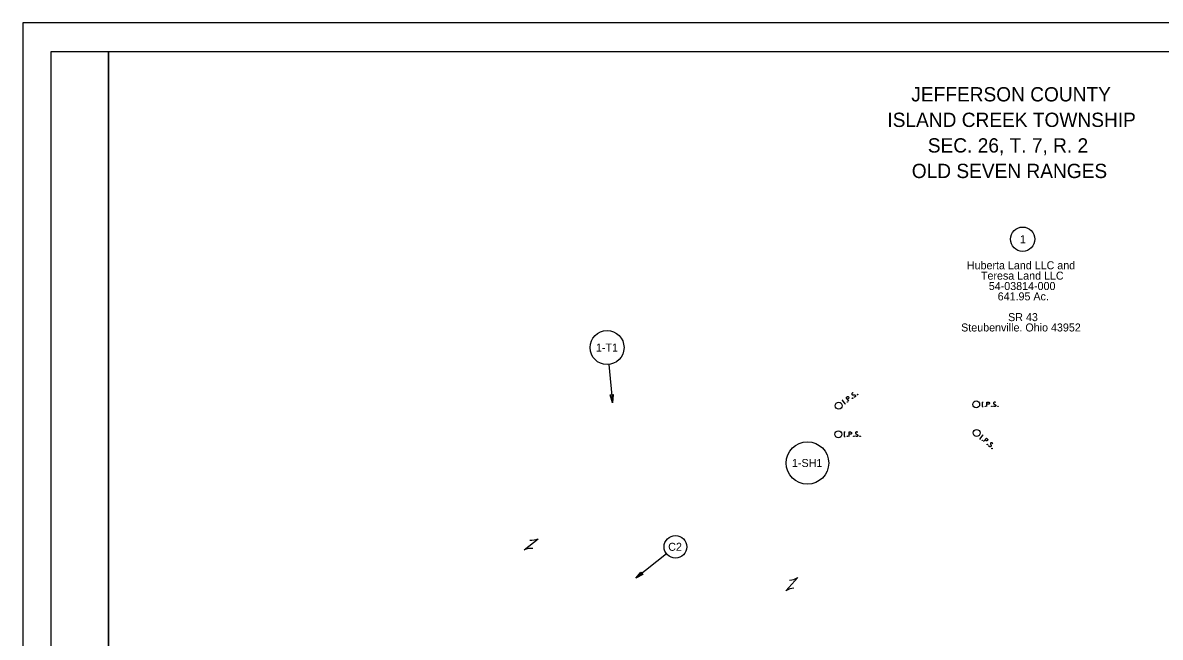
# Model space of a CAD drawing. Extents: x 0 to 85331, y -29864 to 440.
# Drawn here: x 0 to 398, y 225.2 to 440 of the extents above; entities that cross this region are included whole.
import ezdxf

# ---------------------------------------------------------------- set-up
doc = ezdxf.new("R2010")
doc.units = 0
for name, color, linetype in [('GE_X_Cells', 7, 'Continuous'), ('SG_X_PullBox', 7, 'Continuous'), ('SN_X_Public', 7, 'Continuous'), ('SV_X_Random_Point', 7, 'Continuous'), ('SV_X_Shot_Marker', 7, 'Continuous'), ('UT_X_Telecom_Cells', 7, 'Continuous')]:
    doc.layers.add(name, color=color, linetype=linetype)

msp = doc.modelspace()

# ---------------------------------------------------------------- linework, layer by layer
at = {"layer": 'GE_X_Cells'}
msp.add_lwpolyline([(0, 0), (680, 0), (680, 440), (0, 440)], close=True, dxfattribs=at)
at = {"layer": 'SG_X_PullBox'}
for points in [[(290.62, 310.64), (290.59, 310.65), (290.55, 310.65), (290.44, 310.62), (290.33, 310.57), (290.26, 310.52), (290.23, 310.5), (290.14, 310.39), (290.08, 310.25), (290.08, 310.13), (290.12, 310.03), (290.17, 309.97), (290.24, 309.9), (290.37, 309.88), (291.08, 309.93), (291.15, 309.92), (291.2, 309.89), (291.26, 309.85), (291.31, 309.78), (291.34, 309.72), (291.36, 309.67), (291.38, 309.6), (291.39, 309.55), (291.4, 309.51), (291.39, 309.46), (291.38, 309.42), (291.36, 309.37), (291.34, 309.34), (291.27, 309.27), (291.14, 309.18), (291.05, 309.15), (290.88, 309.13), (290.76, 309.14)], [(286.7, 307.96), (286.99, 308.16)], [(287.78, 306.76), (286.84, 308.06)], [(287.64, 306.66), (287.92, 306.86)], [(289.05, 307.68), (288.11, 308.97), (288.54, 309.28), (288.59, 309.3), (288.67, 309.33), (288.71, 309.33), (288.75, 309.33), (288.83, 309.3), (288.89, 309.27), (288.97, 309.2), (289.06, 309.08), (289.08, 309.03), (289.1, 308.96), (289.12, 308.86), (289.11, 308.8), (289.09, 308.76), (289.06, 308.71), (289, 308.65), (288.57, 308.34)], [(288.43, 307.49), (288.48, 307.53), (288.52, 307.53), (288.57, 307.5), (288.61, 307.45), (288.61, 307.39), (288.6, 307.35), (288.56, 307.32), (288.52, 307.32), (288.46, 307.34), (288.42, 307.39), (288.42, 307.46), (288.43, 307.49)], [(290.26, 308.81), (290.3, 308.84), (290.34, 308.84), (290.4, 308.82), (290.44, 308.77), (290.44, 308.71), (290.43, 308.67), (290.38, 308.64), (290.34, 308.64), (290.28, 308.66), (290.25, 308.71), (290.24, 308.77), (290.26, 308.81)], [(292.03, 310.09), (292.07, 310.12), (292.11, 310.12), (292.17, 310.09), (292.21, 310.04), (292.21, 309.98), (292.2, 309.94), (292.15, 309.91), (292.11, 309.91), (292.05, 309.93), (292.02, 309.99), (292.01, 310.05), (292.03, 310.09)], [(335.66, 307.4), (336.01, 307.4)], [(335.84, 305.8), (335.84, 307.4)], [(337.4, 305.8), (337.4, 307.4), (337.93, 307.4), (337.99, 307.38), (338.06, 307.36), (338.1, 307.33), (338.13, 307.31), (338.17, 307.25), (338.21, 307.18), (338.23, 307.08), (338.23, 306.93), (338.22, 306.88), (338.2, 306.8), (338.15, 306.72), (338.11, 306.68), (338.07, 306.65), (338.02, 306.63), (337.93, 306.62), (337.4, 306.62)], [(340.41, 307.28), (340.39, 307.31), (340.36, 307.33), (340.26, 307.37), (340.14, 307.4), (340.05, 307.4), (340.01, 307.4), (339.87, 307.36), (339.75, 307.28), (339.67, 307.18), (339.65, 307.08), (339.65, 307.01), (339.67, 306.91), (339.76, 306.82), (340.37, 306.44), (340.42, 306.39), (340.44, 306.34), (340.47, 306.26), (340.47, 306.19), (340.45, 306.11), (340.44, 306.06), (340.42, 306), (340.4, 305.95), (340.38, 305.91), (340.34, 305.87), (340.31, 305.85), (340.27, 305.82), (340.23, 305.81), (340.14, 305.8), (339.98, 305.8), (339.88, 305.82), (339.74, 305.91), (339.65, 305.99)], [(335.66, 305.8), (336.01, 305.8)], [(336.8, 306.01), (336.85, 306.01), (336.88, 305.99), (336.92, 305.94), (336.92, 305.87), (336.88, 305.82), (336.85, 305.8), (336.8, 305.8), (336.76, 305.82), (336.73, 305.87), (336.73, 305.94), (336.76, 305.99), (336.8, 306.01)], [(339.04, 306.01), (339.1, 306.01), (339.13, 305.99), (339.17, 305.94), (339.17, 305.87), (339.13, 305.82), (339.1, 305.8), (339.04, 305.8), (339.01, 305.82), (338.98, 305.87), (338.98, 305.94), (339.01, 305.99), (339.04, 306.01)], [(341.23, 306.01), (341.28, 306.01), (341.31, 305.99), (341.35, 305.94), (341.35, 305.87), (341.31, 305.82), (341.28, 305.8), (341.23, 305.8), (341.19, 305.82), (341.16, 305.87), (341.16, 305.94), (341.19, 305.99), (341.23, 306.01)], [(287.41, 296.93), (287.76, 296.93)], [(287.41, 295.33), (287.76, 295.33)], [(287.59, 295.33), (287.59, 296.93)], [(288.55, 295.54), (288.6, 295.54), (288.63, 295.52), (288.67, 295.47), (288.67, 295.4), (288.63, 295.35), (288.6, 295.33), (288.55, 295.33), (288.51, 295.35), (288.48, 295.4), (288.48, 295.47), (288.51, 295.52), (288.55, 295.54)], [(289.15, 295.33), (289.15, 296.93), (289.68, 296.93), (289.74, 296.91), (289.81, 296.89), (289.85, 296.86), (289.88, 296.84), (289.92, 296.78), (289.96, 296.71), (289.98, 296.61), (289.98, 296.46), (289.97, 296.41), (289.95, 296.34), (289.9, 296.25), (289.86, 296.21), (289.82, 296.18), (289.77, 296.16), (289.68, 296.15), (289.15, 296.15)], [(290.79, 295.54), (290.85, 295.54), (290.88, 295.52), (290.92, 295.47), (290.92, 295.4), (290.88, 295.35), (290.85, 295.33), (290.79, 295.33), (290.76, 295.35), (290.73, 295.4), (290.73, 295.47), (290.76, 295.52), (290.79, 295.54)], [(292.16, 296.81), (292.14, 296.84), (292.11, 296.86), (292.01, 296.9), (291.89, 296.93), (291.8, 296.93), (291.76, 296.93), (291.62, 296.89), (291.5, 296.81), (291.42, 296.71), (291.4, 296.61), (291.4, 296.54), (291.42, 296.44), (291.51, 296.35), (292.12, 295.97), (292.17, 295.92), (292.19, 295.87), (292.22, 295.79), (292.22, 295.72), (292.21, 295.64), (292.19, 295.59), (292.17, 295.53), (292.15, 295.48), (292.13, 295.44), (292.1, 295.4), (292.06, 295.38), (292.02, 295.35), (291.99, 295.34), (291.89, 295.33), (291.73, 295.33), (291.63, 295.35), (291.49, 295.44), (291.4, 295.52)], [(292.98, 295.54), (293.03, 295.54), (293.07, 295.52), (293.1, 295.47), (293.1, 295.4), (293.07, 295.35), (293.03, 295.33), (292.98, 295.33), (292.94, 295.35), (292.91, 295.4), (292.91, 295.47), (292.94, 295.52), (292.98, 295.54)], [(334.82, 294.69), (335.09, 294.46)], [(334.96, 294.57), (335.99, 295.8)], [(335.85, 295.91), (336.12, 295.68)], [(336.16, 293.57), (337.19, 294.79), (337.59, 294.45), (337.63, 294.4), (337.67, 294.34), (337.68, 294.29), (337.69, 294.25), (337.68, 294.18), (337.66, 294.11), (337.62, 294.02), (337.52, 293.9), (337.48, 293.87), (337.41, 293.83), (337.32, 293.79), (337.26, 293.79), (337.22, 293.79), (337.16, 293.8), (337.09, 293.85), (336.68, 294.19)], [(335.83, 294.12), (335.87, 294.08), (335.88, 294.04), (335.87, 293.98), (335.83, 293.94), (335.78, 293.92), (335.74, 293.92), (335.69, 293.96), (335.68, 294), (335.69, 294.06), (335.73, 294.1), (335.79, 294.12), (335.83, 294.12)], [(337.55, 292.67), (337.59, 292.64), (337.6, 292.6), (337.6, 292.54), (337.56, 292.49), (337.5, 292.47), (337.46, 292.47), (337.41, 292.51), (337.41, 292.55), (337.41, 292.61), (337.45, 292.66), (337.51, 292.67), (337.55, 292.67)], [(339.42, 292.77), (339.42, 292.8), (339.41, 292.84), (339.36, 292.93), (339.28, 293.03), (339.21, 293.09), (339.19, 293.11), (339.05, 293.17), (338.91, 293.19), (338.79, 293.17), (338.71, 293.1), (338.66, 293.04), (338.61, 292.95), (338.62, 292.83), (338.84, 292.15), (338.85, 292.08), (338.83, 292.02), (338.8, 291.95), (338.75, 291.89), (338.7, 291.84), (338.66, 291.81), (338.6, 291.78), (338.55, 291.75), (338.51, 291.74), (338.46, 291.73), (338.42, 291.73), (338.37, 291.74), (338.33, 291.75), (338.25, 291.81), (338.13, 291.91), (338.07, 291.99), (338.02, 292.15), (338, 292.26)], [(339.22, 291.27), (339.27, 291.23), (339.27, 291.19), (339.27, 291.13), (339.23, 291.08), (339.17, 291.07), (339.13, 291.07), (339.09, 291.1), (339.08, 291.14), (339.08, 291.2), (339.12, 291.25), (339.18, 291.27), (339.22, 291.27)]]:
    msp.add_lwpolyline(points, dxfattribs=at)
for centre in [(285.53, 306.12), (333.64, 306.59), (285.39, 296.13), (333.79, 296.6)]:
    msp.add_circle(centre, 1.2, dxfattribs=at)
at = {"layer": 'SN_X_Public'}
for p, q in [((175.48, 255.7), (180.36, 259.61)), ((177.92, 257.65), (177.92, 257.65)), ((271.17, 246.05), (267.02, 241.38)), ((269.1, 243.72), (269.1, 243.72))]:
    msp.add_line(p, q, dxfattribs=at)
for centre, start, end in [((178.12, 264.45), 262.1767, 294.8192), ((177.72, 250.86), 82.1767, 114.8192), ((268.15, 250.45), 271.8231, 304.4656), ((270.04, 236.98), 91.8231, 124.4656)]:
    msp.add_arc(centre, 5.34, start, end, dxfattribs=at)
at = {"layer": 'SV_X_Random_Point'}
for points in [[(10, 430), (30, 430), (30, 10), (10, 10)], [(30, 430), (670, 430), (670, 10), (30, 10)]]:
    msp.add_lwpolyline(points, close=True, dxfattribs=at)
at = {"layer": 'UT_X_Telecom_Cells'}
for p, q in [((205.03, 320.52), (206.35, 307.14)), ((225.27, 254.33), (214.48, 245.78))]:
    msp.add_line(p, q, dxfattribs=at)
for points in [[(205.52, 309.87), (206.64, 309.98), (206.35, 307.14)], [(216.33, 247.95), (217.02, 247.08), (214.48, 245.78)]]:
    msp.add_lwpolyline(points, close=True, dxfattribs=at)
for centre, radius in [((349.88, 364.33), 4.24), ((204.45, 326.43), 5.94), ((274.58, 286.08), 7.43), ((228.38, 256.79), 3.96)]:
    msp.add_circle(centre, radius, dxfattribs=at)

# ---------------------------------------------------------------- texts
at = {"layer": 'SV_X_Shot_Marker'}
for s, p in [('             JEFFERSON COUNTY             ', (286.77, 412.5)), ('           ISLAND CREEK TOWNSHIP          ', (282.12, 403.57)), ('            SEC. 26, T. 7, R. 2           ', (294.4, 394.63)), ('             OLD SEVEN RANGES             ', (286.93, 385.7))]:
    msp.add_text(s, height=5, dxfattribs=at).set_placement(p)
at = {"layer": 'UT_X_Telecom_Cells'}
for s, p in [('1', (348.95, 362.93)), ('Huberta Land LLC and', (330.37, 353.81)), ('Teresa Land LLC', (335.29, 350.19)), ('54-03814-000', (338.04, 346.56)), ('641.95 Ac.', (341.15, 342.94)), ('SR 43', (344.8, 335.69)), ('Steubenville. Ohio 43952', (328.37, 332.07)), ('1-T1', (200.58, 325.03)), ('1-SH1', (269.18, 284.68)), ('C2', (225.86, 255.39))]:
    msp.add_text(s, height=2.8, dxfattribs=at).set_placement(p)

doc.saveas('drawing.dxf')
